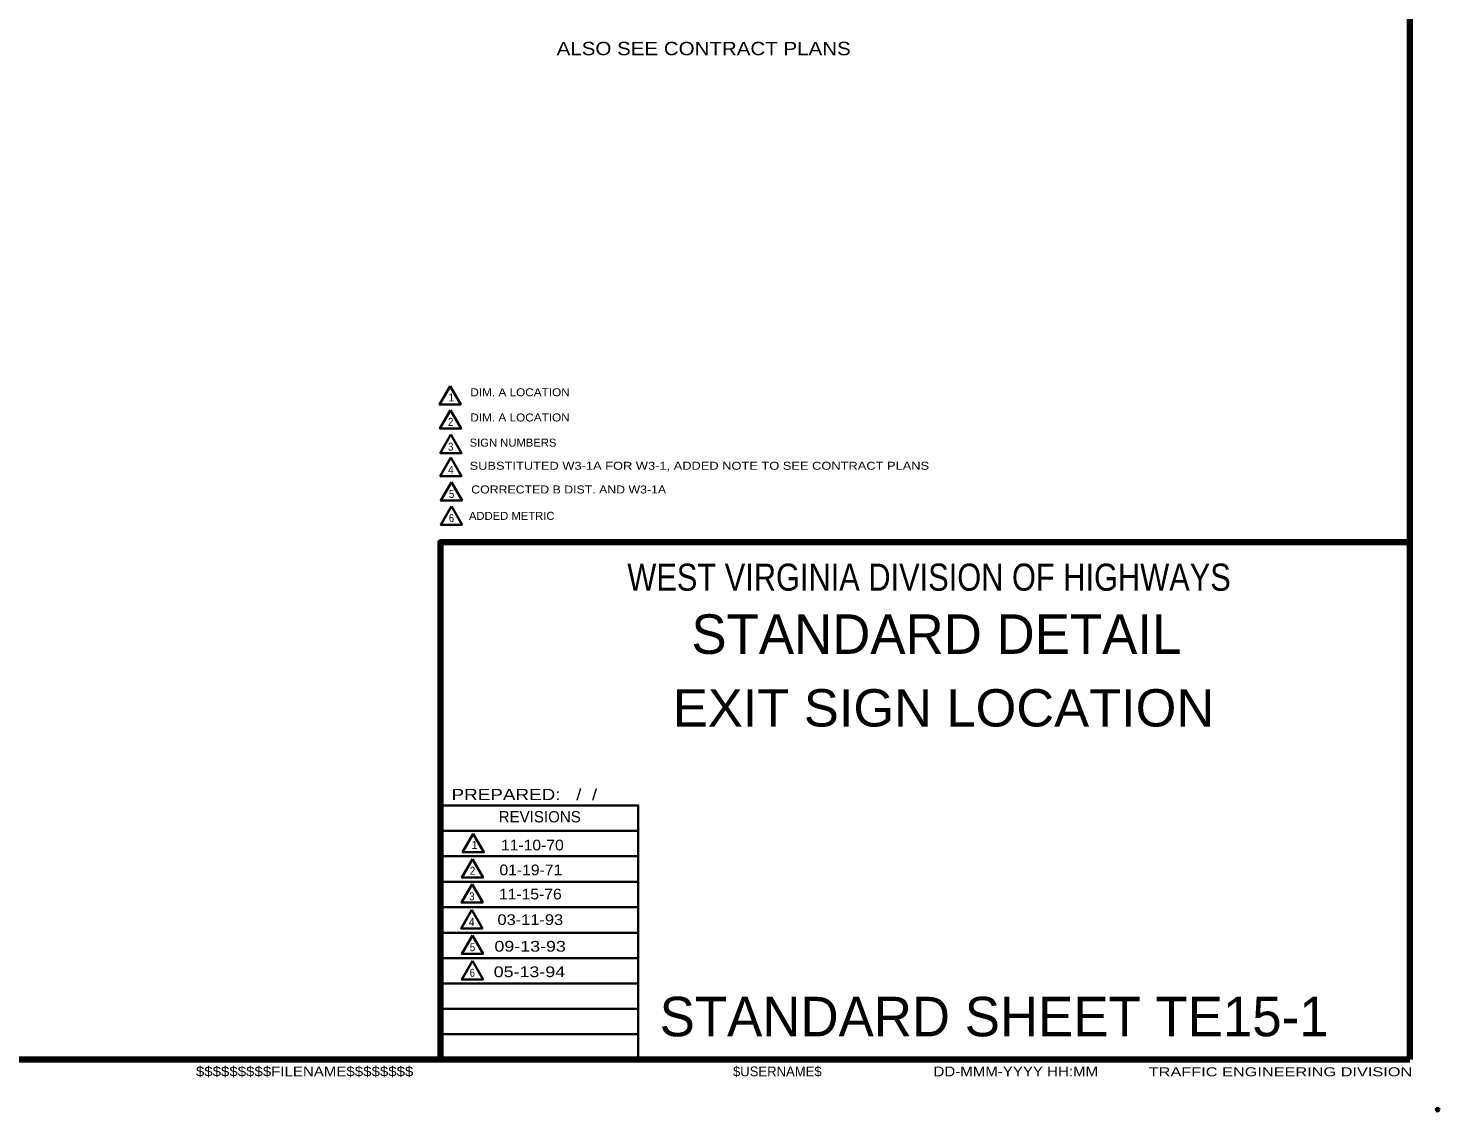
# Model space of a CAD drawing. Extents: x -371 to 484, y -338 to 206.
# Drawn here: x 166.8 to 484, y -338 to -94.6 of the extents above; entities that cross this region are included whole.
import ezdxf
from ezdxf.enums import TextEntityAlignment as Align

# ---------------------------------------------------------------- set-up
doc = ezdxf.new("R2010")
doc.units = 0
doc.header["$PDMODE"] = 32
doc.header["$PDSIZE"] = 0.5
doc.layers.add('1', color=7, linetype='Continuous', lineweight=53)
doc.layers.add('61', color=7, linetype='Continuous', lineweight=35)

msp = doc.modelspace()

# ---------------------------------------------------------------- linework, layer by layer
at = {"layer": '1', "lineweight": 158}
for q in [(477.495, 199.606), (477.495, -210.194), (-314.105, -326.494)]:
    msp.add_line((477.495, -326.494), q, dxfattribs=at)
at = {"layer": '1', "lineweight": 13}
msp.add_line((477.495, -326.494), (477.495, 199.606), dxfattribs=at)
at = {"layer": '1', "lineweight": 35}
for p, q in [((303.995, -275.094), (259.495, -275.094)), ((303.995, -280.794), (259.495, -280.794)), ((303.995, -286.594), (259.495, -286.594)), ((303.995, -292.294), (259.495, -292.294)), ((303.995, -297.994), (259.495, -297.994)), ((303.995, -303.694), (259.495, -303.694)), ((303.995, -309.394), (259.495, -309.394)), ((303.995, -315.094), (259.495, -315.094)), ((303.995, -320.794), (259.495, -320.794))]:
    msp.add_line(p, q, dxfattribs=at)
for points in [[(261.66, -175.097), (259.26, -179.254), (264.06, -179.254)], [(261.773, -180.479), (259.373, -184.636), (264.173, -184.636)], [(261.851, -185.976), (259.451, -190.133), (264.251, -190.133)], [(261.851, -191.169), (259.451, -195.326), (264.251, -195.326)], [(261.982, -196.671), (259.582, -200.828), (264.382, -200.828)], [(261.982, -202.096), (259.582, -206.253), (264.382, -206.253)], [(266.883, -275.737), (264.483, -279.894), (269.283, -279.894)], [(266.684, -281.43), (264.284, -285.587), (269.084, -285.587)], [(266.607, -287.083), (264.207, -291.24), (269.007, -291.24)], [(266.526, -292.868), (264.126, -297.025), (268.926, -297.025)], [(266.675, -298.62), (264.275, -302.777), (269.075, -302.777)], [(266.675, -304.356), (264.275, -308.513), (269.075, -308.513)]]:
    msp.add_lwpolyline(points, close=True, dxfattribs=at)
at = {"layer": '1', "lineweight": 158}
msp.add_lwpolyline([(259.495, -326.494), (259.495, -210.194), (477.495, -210.194)], dxfattribs=at)
at = {"layer": '1', "lineweight": 35}
msp.add_lwpolyline([(303.995, -326.494), (303.995, -269.394), (259.495, -269.394)], dxfattribs=at)
at = {"layer": '1'}
msp.add_point((483.795, -337.794), dxfattribs=at)
at = {"layer": '61', "lineweight": 53}
for q in [(324.795, -326.494), (324.795, -326.494), (324.795, -326.494), (325.095, -326.494), (325.095, -326.494)]:
    msp.add_line((477.495, -326.494), q, dxfattribs=at)

# ---------------------------------------------------------------- texts
at = {"layer": '1'}
for s, height, width, p in [('ALSO SEE CONTRACT PLANS', 3, 1.15, (318.708, -100.676)), ('WEST VIRGINIA DIVISION OF HIGHWAYS', 6.089, 0.85, (369.395, -221.094)), ('EXIT SIGN LOCATION', 8.391, 1.05, (372.657, -251.636)), ('11-10-70', 2.4, 1.1, (280.176, -279.491)), ('01-19-71', 2.4, 1.1, (279.84, -285.082)), ('11-15-76', 2.4, 1.1, (279.709, -290.518)), ('03-11-93', 2.4, 1.15, (279.709, -296.265)), ('09-13-93', 2.4, 1.25, (279.672, -302.252)), ('05-13-94', 2.4, 1.25, (279.512, -307.988))]:
    msp.add_text(s, height=height, dxfattribs=dict(at, width=width)).set_placement(p, align=Align.CENTER)
for s, height, p in [('1', 1.8, (261.278, -178.523)), ('REVISIONS', 2.537, (272.595, -273.194)), ('1', 1.8, (266.5, -279.163)), ('STANDARD SHEET TE15-1', 8.881, (308.795, -321.294)), ('$USERNAME$', 2.2, (325.295, -330.294))]:
    msp.add_text(s, height=height, dxfattribs=at).set_placement(p)
for s, height, width, p in [('DIM. A LOCATION', 1.8, 1.1, (266.214, -177.374)), ('2', 1.8, 0.9, (261.201, -184.035)), ('DIM. A LOCATION', 1.8, 1.1, (266.214, -183.039)), ('SIGN NUMBERS', 1.8, 1.05, (266.061, -188.704)), ('3', 1.8, 0.9, (261.201, -189.623)), ('4', 1.8, 0.95, (261.201, -194.817)), ('SUBSTITUTED W3-1A FOR W3-1, ADDED NOTE TO SEE CONTRACT PLANS', 1.8, 1.2, (266.061, -193.898)), ('5', 1.8, 0.9, (261.41, -200.227)), ('CORRECTED B DIST. AND W3-1A', 1.8, 1.15, (266.423, -199.232)), ('6', 1.8, 0.85, (261.41, -205.652)), ('ADDED METRIC', 1.8, 1.05, (265.914, -205.165)), ('PREPARED:   /  /  ', 2.537, 1.25, (261.995, -268.194)), ('2', 1.8, 0.9, (266.112, -284.986)), ('3', 1.8, 0.9, (265.957, -290.731)), ('4', 1.8, 0.95, (265.875, -296.516)), ('5', 1.8, 0.9, (266.103, -302.176)), ('6', 1.8, 0.85, (266.103, -307.912)), ('$$$$$$$$$FILENAME$$$$$$$$', 2.2, 1.15, (204.495, -330.294)), ('DD-MMM-YYYY HH:MM', 2.2, 1.15, (370.395, -330.294)), ('TRAFFIC ENGINEERING DIVISION', 2.031, 1.35, (418.795, -330.294))]:
    msp.add_text(s, height=height, dxfattribs=dict(at, width=width)).set_placement(p)
msp.add_text('STANDARD DETAIL', height=8.881, dxfattribs=at).set_placement((371.045, -235.294), align=Align.CENTER)

doc.saveas('drawing.dxf')
